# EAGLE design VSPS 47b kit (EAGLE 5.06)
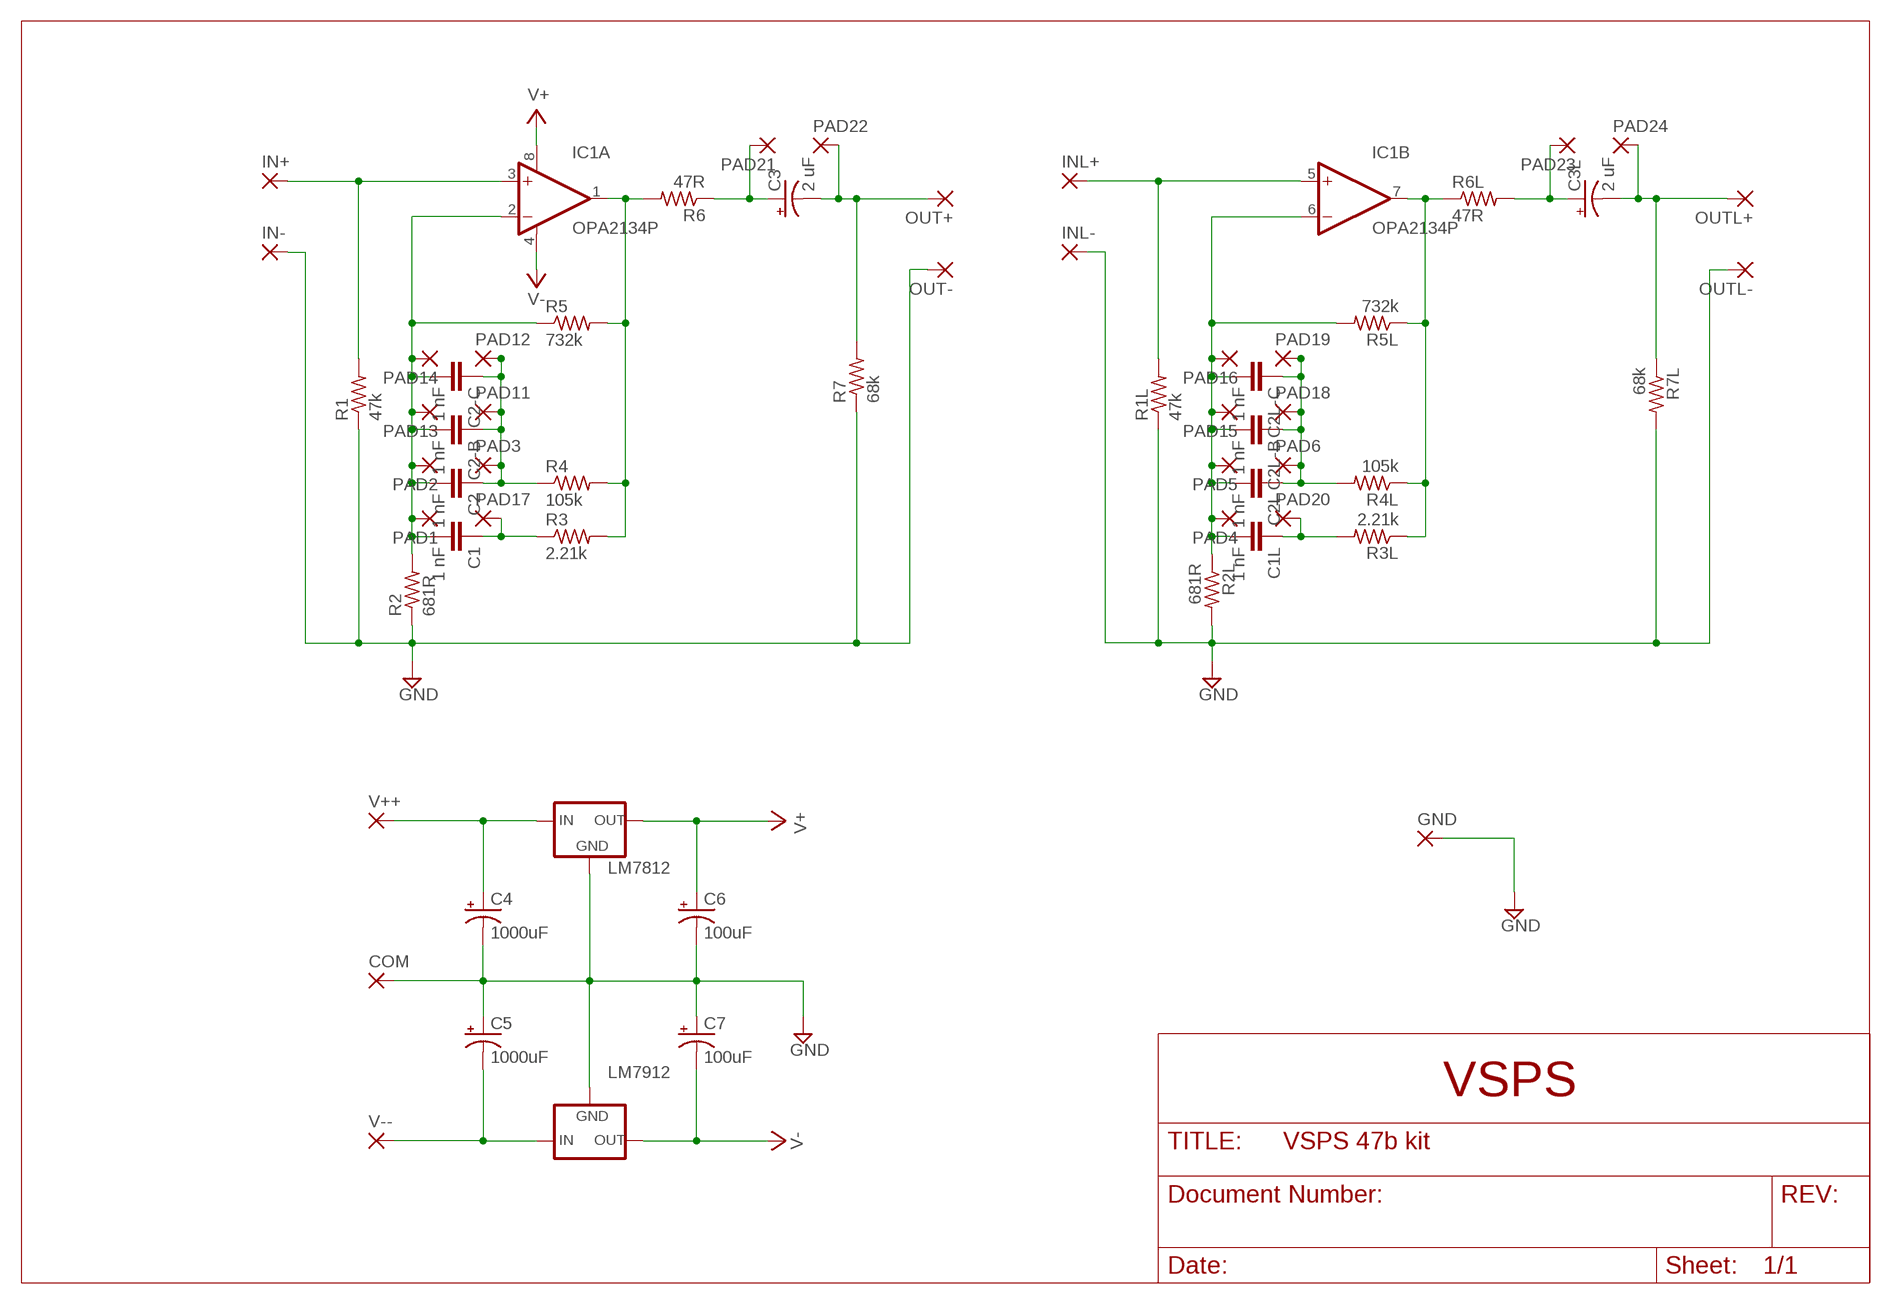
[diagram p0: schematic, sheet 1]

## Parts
C1  1 nF  C-EU050-045X075  [C050-045X075]
C1L  1 nF  C-EU050-045X075  [C050-045X075]
C2  1 nF  C-EU050-045X075  [C050-045X075]
C2-B  1 nF  C-EU050-045X075  [C050-045X075]
C2-C  1 nF  C-EU050-045X075  [C050-045X075]
C2L  1 nF  C-EU050-045X075  [C050-045X075]
C2L-B  1 nF  C-EU050-045X075  [C050-045X075]
C2L-C  1 nF  C-EU050-045X075  [C050-045X075]
C3  2 uF  CPOL-USE2.5-5  [E2,5-5]
C3L  2 uF  CPOL-USE2.5-5  [E2,5-5]
C4  1000uF  CPOL-USE5-10.5  [E5-10,5]
C5  1000uF  CPOL-USE5-10.5  [E5-10,5]
C6  100uF  CPOL-USE2.5-6  [E2,5-6]
C7  100uF  CPOL-USE2.5-6  [E2,5-6]
COM  2,54/1,0  [2,54/1,0]
GND  2,54/1,0  [2,54/1,0]
IC1  OPA2134P  [DIL08]
IN+  2,54/1,0  [2,54/1,0]
IN-  2,54/1,0  [2,54/1,0]
INL+  2,54/1,0  [2,54/1,0]
INL-  2,54/1,0  [2,54/1,0]
LM7812  78XXS  [78XXS]
LM7912  79XXS  [79XXS]
OUT+  2,54/1,0  [2,54/1,0]
OUT-  2,54/1,0  [2,54/1,0]
OUTL+  2,54/1,0  [2,54/1,0]
OUTL-  2,54/1,0  [2,54/1,0]
PAD1  1,6/0,9-SS  [1,6/0,9-SS]
PAD2  1,6/0,9-SS  [1,6/0,9-SS]
PAD3  1,6/0,9-SS  [1,6/0,9-SS]
PAD4  1,6/0,9-SS  [1,6/0,9-SS]
PAD5  1,6/0,9-SS  [1,6/0,9-SS]
PAD6  1,6/0,9-SS  [1,6/0,9-SS]
PAD11  1,6/0,9-SS  [1,6/0,9-SS]
PAD12  1,6/0,9-SS  [1,6/0,9-SS]
PAD13  1,6/0,9-SS  [1,6/0,9-SS]
PAD14  1,6/0,9-SS  [1,6/0,9-SS]
PAD15  1,6/0,9-SS  [1,6/0,9-SS]
PAD16  1,6/0,9-SS  [1,6/0,9-SS]
PAD17  1,6/0,9-SS  [1,6/0,9-SS]
PAD18  1,6/0,9-SS  [1,6/0,9-SS]
PAD19  1,6/0,9-SS  [1,6/0,9-SS]
PAD20  1,6/0,9-SS  [1,6/0,9-SS]
PAD21  2,54/1,0  [2,54/1,0]
PAD22  2,54/1,0  [2,54/1,0]
PAD23  2,54/1,0  [2,54/1,0]
PAD24  2,54/1,0  [2,54/1,0]
R1  47k  R-US_0207/10  [0207/10]
R1L  47k  R-US_0207/10  [0207/10]
R2  681R  R-US_0207/10  [0207/10]
R2L  681R  R-US_0207/10  [0207/10]
R3  2.21k  R-US_0207/10  [0207/10]
R3L  2.21k  R-US_0207/10  [0207/10]
R4  105k  R-US_0207/10  [0207/10]
R4L  105k  R-US_0207/10  [0207/10]
R5  732k  R-US_0207/10  [0207/10]
R5L  732k  R-US_0207/10  [0207/10]
R6  47R  R-US_0207/10  [0207/10]
R6L  47R  R-US_0207/10  [0207/10]
R7  68k  R-US_0207/10  [0207/10]
R7L  68k  R-US_0207/10  [0207/10]
V++  2,54/1,0  [2,54/1,0]
V--  2,54/1,0  [2,54/1,0]

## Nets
GND: C4.- C5.+ C6.- C7.+ COM.1(P) GND.1(P) IN-.1(P) INL-.1(P) LM7812.GND LM7912.GND OUT-.1(P) OUTL-.1(P) R1.1 R1L.1 R2.1 R2L.2 R7.1 R7L.2
N$1: IC1.3(A:+IN) IN+.1(P) R1.2
N$2: C3.+ PAD21.1(P) R6.1
N$3: IC1.1(A:OUT) R3.2 R4.2 R5.2 R6.2
N$7: IC1.5(B:+IN) INL+.1(P) R1L.2
N$8: C3L.- OUTL+.1(P) PAD24.1(P) R7L.1
N$9: C3L.+ PAD23.1(P) R6L.2
N$10: IC1.7(B:OUT) R3L.1 R4L.1 R5L.1 R6L.1
N$12: C1.1 PAD17.1(P) R3.1
N$13: C1L.1 PAD20.1(P) R3L.2
N$18: C3.- OUT+.1(P) PAD22.1(P) R7.2
RIAA-1: C1.2 C2-B.2 C2-C.2 C2.2 IC1.2(A:-IN) PAD1.1(P) PAD2.1(P) PAD13.1(P) PAD14.1(P) R2.2 R5.1
RIAA-1A: C1L.2 C2L-B.2 C2L-C.2 C2L.2 IC1.6(B:-IN) PAD4.1(P) PAD5.1(P) PAD15.1(P) PAD16.1(P) R2L.1 R5L.2
RIAA-2: C2-B.1 C2-C.1 C2.1 PAD3.1(P) PAD11.1(P) PAD12.1(P) R4.1
RIAA-2A: C2L-B.1 C2L-C.1 C2L.1 PAD6.1(P) PAD18.1(P) PAD19.1(P) R4L.2
V+: C6.+ IC1.8(A:V+) LM7812.OUT
V++: C4.+ LM7812.IN V++.1(P)
V-: C7.- IC1.4(A:V-) LM7912.OUT
V--: C5.- LM7912.IN V--.1(P)

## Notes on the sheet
- VSPS

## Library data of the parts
C1 C1L C2 C2-B C2-C C2L C2L-B C2L-C = rcl:C-EU: CAPACITOR, European symbol
C3 C3L C4-C7 = rcl:CPOL-US: POLARIZED CAPACITOR, American symbol
COM GND IN+ IN- INL+ INL- OUT+ OUT- OUTL+ OUTL- PAD21-PAD24 V++ V-- = wirepad:2,54/1,0: THROUGH-HOLE PAD
IC1 = burr-brown:OPA2134: Operational Amplifier
LM7812 = v-reg:78XXS: VOLTAGE REGULATOR
LM7912 = v-reg:79XXS: VOLTAGE REGULATOR
PAD1-PAD6 PAD11-PAD20 = wirepad:1,6/0,9-SS: Through hole pad
R1 R1L R2 R2L R3 R3L R4 R4L R5 R5L R6 R6L R7 R7L = rcl:R-US_: RESISTOR, American symbol

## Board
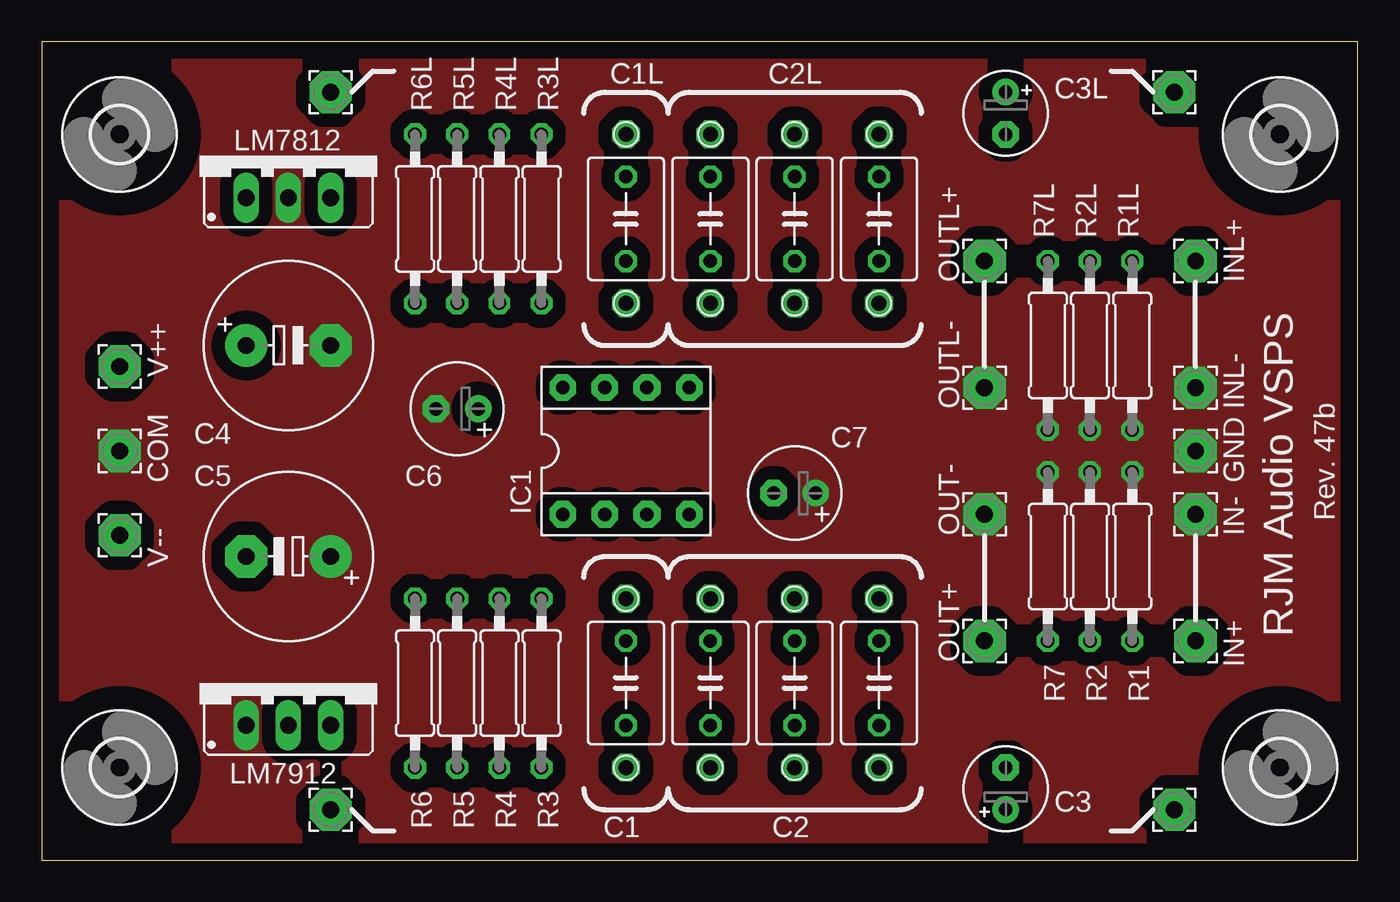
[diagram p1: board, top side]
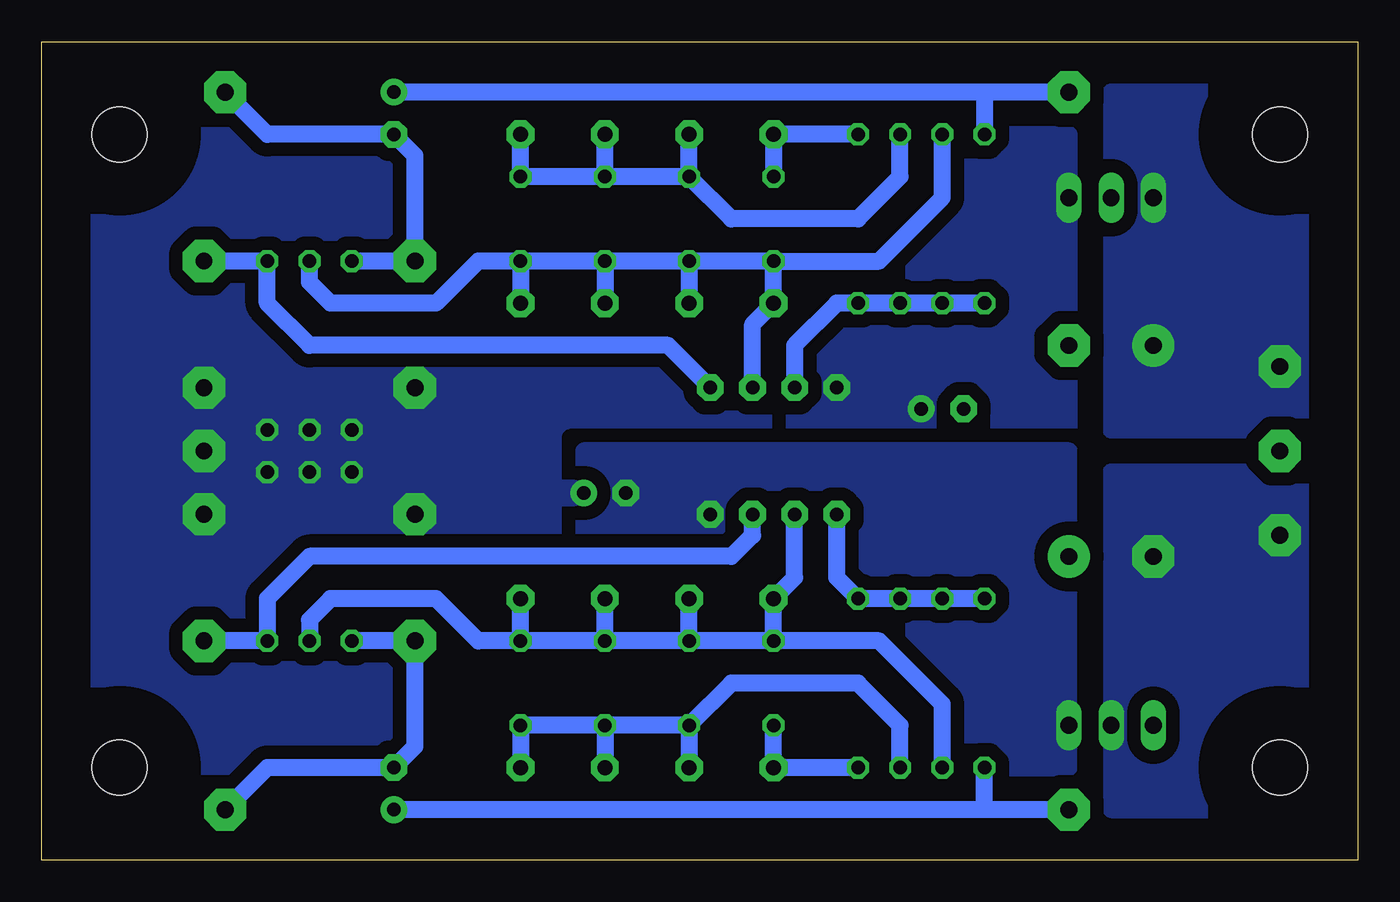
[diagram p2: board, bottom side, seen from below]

Size 79.25 x 49.28 mm. Coordinates in mm from the lower left corner, seen from the top.
Outline: 0,0 79.25,0 79.25,49.28 0,49.28 0,0
Copper layers (1*16): Top 0.035mm / dielectric 1.5mm / Bottom 0.035mm
Design rules "10mils": minimum track width 10mil, minimum drill 24mil, track to track 10mil, track to pad 10mil, pad to pad 10mil, via to via 10mil, smd to smd 10mil, copper to edge 40mil, drill to drill 10mil, minimum pad ring 10mil, minimum via ring 8mil, stop-mask expansion 0mil, vias tented up to drill 0mil, thermal gap 10mil

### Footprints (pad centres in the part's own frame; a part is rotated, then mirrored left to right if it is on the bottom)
C050-045X075 = drill 0.813 octagon: 1 -2.54,0; 2 2.54,0
E2,5-5 = drill 0.813 pad 1.6 round: + -1.27,0 | drill 0.813 pad 1.6 octagon: - 1.27,0
E5-10,5 = drill 1.016 pad 2.54 round: + -2.54,0 | drill 1.016 pad 2.54 octagon: - 2.54,0
E2,5-6 = drill 0.813 pad 1.6 round: + -1.27,0 | drill 0.813 pad 1.6 octagon: - 1.27,0
2,54/1,0 = drill 1.016 pad 2.54 octagon: 1 0,0
DIL08 = drill 0.813 pad 1.6 octagon: 1 -3.81,-3.81; 2 -1.27,-3.81; 3 1.27,-3.81; 4 3.81,-3.81; 5 3.81,3.81; 6 1.27,3.81; 7 -1.27,3.81; 8 -3.81,3.81
78XXS = drill 1.016 long: GND 0,-2.54; IN -2.54,-2.54; OUT 2.54,-2.54
79XXS = drill 1.016 long: GND -2.54,-2.54; IN 0,-2.54; OUT 2.54,-2.54
1,6/0,9-SS = drill 0.9 pad 1.676 octagon: 1 0,0
0207/10 = drill 0.813 octagon: 1 -5.08,0; 2 5.08,0
3,3 = hole 3.3: 0,0

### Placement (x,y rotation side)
C1  35.18,10.67 90 top
C1L  35.18,38.61 270 top
C2  40.26,10.67 90 top
C2-B  45.34,10.67 90 top
C2-C  50.42,10.67 90 top
C2L  40.26,38.61 270 top
C2L-B  45.34,38.61 270 top
C2L-C  50.42,38.61 270 top
C3  58.04,4.32 90 top
C3L  58.04,44.96 270 top
C4  14.86,30.99 0 top
C5  14.86,18.29 180 top
C6  25.02,27.18 180 top
C7  45.34,22.1 180 top
COM  4.7,24.64 0 top
GND  69.47,24.64 0 top
IC1  35.18,24.64 0 top
IN+  69.47,13.21 0 top
IN-  69.47,20.83 0 top
INL+  69.47,36.07 0 top
INL-  69.47,28.45 0 top
LM7812  14.86,42.42 0 top
LM7912  14.86,10.67 0 top
OUT+  56.77,13.21 0 top
OUT-  56.77,20.83 0 top
OUTL+  56.77,36.07 0 top
OUTL-  56.77,28.45 0 top
PAD1  35.18,15.75 0 top
PAD2  45.34,15.75 0 top
PAD3  40.26,5.59 0 top
PAD4  35.18,33.53 0 top
PAD5  40.26,33.53 0 top
PAD6  40.26,43.69 0 top
PAD11  50.42,5.59 0 top
PAD12  45.34,5.59 0 top
PAD13  50.42,15.75 0 top
PAD14  40.26,15.75 0 top
PAD15  50.42,33.53 0 top
PAD16  45.34,33.53 0 top
PAD17  35.18,5.59 0 top
PAD18  50.42,43.69 0 top
PAD19  45.34,43.69 0 top
PAD20  35.18,43.69 0 top
PAD21  17.4,3.05 0 top
PAD22  68.2,3.05 0 top
PAD23  17.4,46.23 0 top
PAD24  68.2,46.23 0 top
R1  65.66,18.29 270 top
R1L  65.66,30.99 90 top
R2  63.12,18.29 270 top
R2L  63.12,30.99 270 top
R3  30.1,10.67 90 top
R3L  30.1,38.61 90 top
R4  27.56,10.67 90 top
R4L  27.56,38.61 90 top
R5  25.02,10.67 90 top
R5L  25.02,38.61 90 top
R6  22.48,10.67 90 top
R6L  22.48,38.61 90 top
R7  60.58,18.29 270 top
R7L  60.58,30.99 270 top
U$1  [3,3]  4.7,43.69 0 top
U$2  [3,3]  74.55,43.69 0 top
U$3  [3,3]  74.55,5.59 0 top
U$4  [3,3]  4.7,5.59 0 top
V++  4.7,29.72 0 top
V--  4.7,19.56 0 top

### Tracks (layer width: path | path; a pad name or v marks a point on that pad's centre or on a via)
GND
  pour Bottom (isolate 0.813, rank 6, no thermals): 33.91,0.51 33.91,48.77 75.82,48.77 75.82,0.51
  pour Top (isolate 0.813, no thermals): 0.89,48.77 78.36,48.77 78.36,0.51 0.89,0.51
N$1
  Bottom 1.016: IC1.3 36.45,19.56 37.72,18.29 63.12,18.29 65.66,15.75 R1.2 IN+.1
N$2
  Bottom 1.016: 22.48,3.05 R6.1 | 22.48,3.05 C3.+ | PAD21.1 22.48,3.05
N$3
  Bottom 1.016: R6.2 R5.2 R4.2 R3.2 31.37,17.02 IC1.1
N$7
  Bottom 1.016: IC1.5 41.53,30.99 63.12,30.99 65.66,33.53 R1L.2 INL+.1
N$8
  Bottom 1.016: R7L.1 OUTL+.1 56.77,42.42 C3L.- 65.66,43.69 PAD24.1
N$9
  Bottom 1.016: 22.48,46.23 R6L.2 | 22.48,46.23 C3L.+ | PAD23.1 22.48,46.23
N$10
  Bottom 1.016: IC1.7 33.91,30.99 31.37,33.53 R3L.1 R4L.1 R5L.1 R6L.1
N$12
  Bottom 1.016: PAD17.1 C1.1 PAD17.1 | R3.1 PAD17.1
N$13
  Bottom 1.016: PAD20.1 C1L.1 PAD20.1 | R3L.2 PAD20.1
N$18
  Bottom 1.016: R7.2 OUT+.1 56.77,6.86 C3.- 65.66,5.59 PAD22.1
RIAA-1
  Bottom 1.016: C1.2 PAD1.1 33.91,17.02 IC1.2 | C2.2 PAD14.1 C2.2 | C2-B.2 PAD2.1 C2-B.2 | C2-C.2 PAD13.1 | C2-C.2 PAD13.1 | C2-B.2 C2-C.2 | C2.2 C2-B.2 | C1.2 C2.2 | C1.2 28.83,13.21 25.02,9.4 R5.1 | C2-C.2 PAD13.1 | C2-C.2 PAD13.1 | C2-C.2 52.96,13.21 55.5,15.75 61.85,15.75 63.12,14.48 R2.2
RIAA-1A
  Bottom 1.016: C1L.2 PAD4.1 36.45,32.26 IC1.6 | C2L.2 PAD5.1 | C2L-B.2 PAD16.1 | C2L-C.2 PAD15.1 | C2L-B.2 C2L-C.2 | C2L.2 C2L-B.2 | C1L.2 C2L.2 | C1L.2 28.83,36.07 25.02,39.88 R5L.2 | C2L-C.2 PAD15.1 | C2L-C.2 PAD15.1 | C2L-C.2 52.96,36.07 55.5,33.53 61.85,33.53 63.12,34.8 R2L.1
RIAA-2
  Bottom 1.016: PAD11.1 C2-C.1 C2-B.1 | C2-B.1 PAD12.1 | C2.1 PAD3.1 | C2.1 C2-B.1 | C2.1 37.72,10.67 30.1,10.67 27.56,8.13 R4.1
RIAA-2A
  Bottom 1.016: C2L.1 PAD6.1 | C2L-B.1 PAD19.1 C2L-B.1 | PAD18.1 C2L-C.1 C2L-B.1 | C2L.1 C2L-B.1 | C2L.1 37.72,38.61 30.1,38.61 27.56,41.15 R4L.2
V+
  pour Bottom (isolate 0.813, rank 5, no thermals): 17.4,43.69 17.4,25.91 33.91,25.91 33.91,43.69
V++
  pour Bottom (isolate 0.813, rank 3, no thermals): 3.43,46.23 14.86,46.23 14.86,25.91 3.43,25.91
V-
  pour Bottom (isolate 0.813, rank 4, no thermals): 17.4,5.59 17.4,24.64 46.61,24.64 46.61,5.59
V--
  pour Bottom (isolate 0.813, rank 3, no thermals): 3.43,3.05 3.43,23.37 14.86,23.37 14.86,3.05

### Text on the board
tPlace: Rev. 47b | RJM Audio VSPS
